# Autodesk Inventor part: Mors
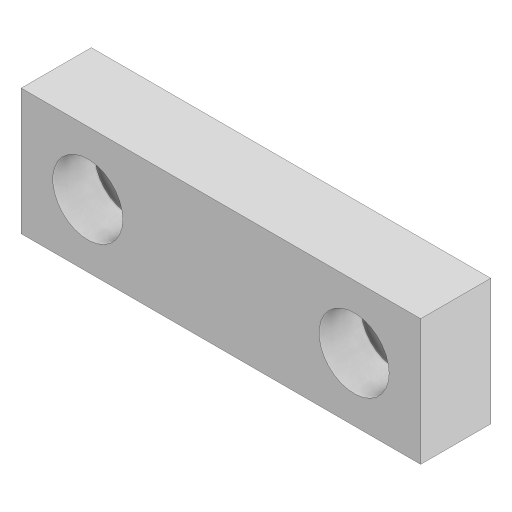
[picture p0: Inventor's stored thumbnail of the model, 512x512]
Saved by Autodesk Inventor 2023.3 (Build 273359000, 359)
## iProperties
Created: 2024-11
Part Number: Mors
Material: Générique
Description: STEP AP203
Document SubType Name: Modeling
Designer: Thier
Density: 1 g/cm^3
Appearance: Par défaut
Title: Mors.STEP
Revision Number: ANY
Sending System: SolidWorks 2017
Preprocessor: SwSTEP 2.0
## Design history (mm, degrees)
feature "Répétition linéaire1"
node "Solide1"
